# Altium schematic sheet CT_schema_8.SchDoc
size 277 x 170 mm
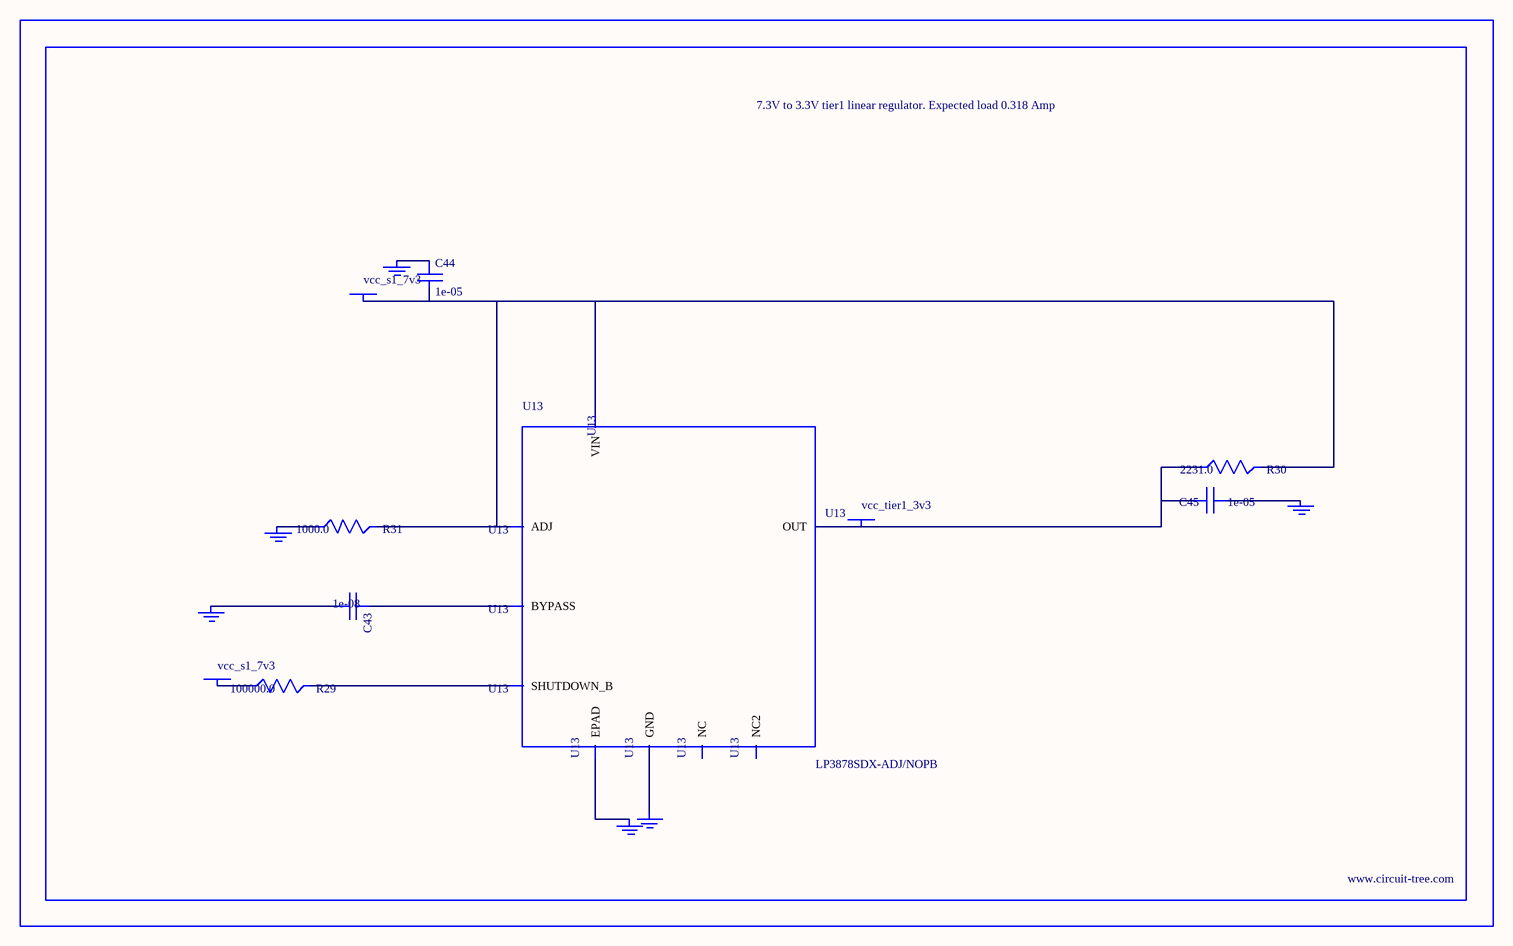
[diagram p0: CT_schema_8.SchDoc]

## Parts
BORDER7  (no value)
C43  1e-08  [C0402]
C44  1e-05  [C1206]
C45  1e-05  [C1210]
GND_INSTANCE_7_0  (no value)
GND_INSTANCE_7_1  (no value)
GND_INSTANCE_7_2  (no value)
GND_INSTANCE_7_3  (no value)
GND_INSTANCE_7_4  (no value)
GND_INSTANCE_7_5  (no value)
POWER_INSTANCE_7_0  vcc_s1_7v3
POWER_INSTANCE_7_1  vcc_s1_7v3
POWER_INSTANCE_7_2  vcc_tier1_3v3
R29  100000.0  [R0603]
R30  2231.0  [R0603]
R31  1000.0  [R0603]
U13  LP3878SDX-ADJ/NOPB  [WSON-8]

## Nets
NetC43_1: C43.1 U13.1(BYPASS)
NetC43_2: C43.2 GND_INSTANCE_7_0.0(GND)
NetC44_1: C44.1 GND_INSTANCE_7_1.0(GND)
NetC44_2: C44.2 POWER_INSTANCE_7_0.0(PWR) R30.2 R31.2 U13.4(VIN) U13.6(ADJ)
NetC45_1: C45.1 GND_INSTANCE_7_2.0(GND)
NetC45_2: C45.2 POWER_INSTANCE_7_2.0(PWR) R30.1 U13.5(OUT)
NetGND_INSTANCE_7_3_0: GND_INSTANCE_7_3.0(GND) R31.1
NetGND_INSTANCE_7_4_0: GND_INSTANCE_7_4.0(GND) U13.PAD(EPAD)
NetGND_INSTANCE_7_5_0: GND_INSTANCE_7_5.0(GND) U13.3(GND)
NetPOWER_INSTANCE_7_1_0: POWER_INSTANCE_7_1.0(PWR) R29.1
NetR29_2: R29.2 U13.8(SHUTDOWN_B)

Not connected (* = marked no-connect by the designer): U13 2(NC) 7(NC2)

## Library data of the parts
BORDER7 = BORDER_PAGE7
C43 = C0402C103K3RAC
C44 = C1206C106K3RACTU
C45 = GRM32DR61E106MA12L
GND_INSTANCE_7_0-GND_INSTANCE_7_5 = GND
POWER_INSTANCE_7_0-POWER_INSTANCE_7_2 = PWR
R29 = RC0603JR-07100KL
R30 = R30
R31 = RC0603JR-071KL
